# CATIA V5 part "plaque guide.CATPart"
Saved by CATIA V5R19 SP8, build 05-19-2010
Part number: plaque guide
Revision: ANY
Definition: UNKNOWN
Nomenclature: plaque guide
Source: Unknown
Bounding box of the stored display mesh (mm): x 0 to 115.86, y -26.87 to 28, z 0 to 3.4
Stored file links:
  D:\Documents\1_Travail\1 - ac-limoges.fr\ac-limoges.fr\Emmanuel Maynard - STI2D_Turgot\2 -2I2D\2_SEQUENCE_Serrure_Biométrique\5-Spé_ITEC\Serrure_Bio_Eleve\plaque guide.CATPart
  D:\Documents\1_Travail\1 - ac-limoges.fr\ac-limoges.fr\Emmanuel Maynard - STI2D_Turgot\2 -2I2D\2_SEQUENCE_Serrure_Biométrique\5-Spé_ITEC\Serrure_Bio_Eleve\0-serrurebio02_eleve.CATProduct
  D:\Documents\1_Travail\1 - ac-limoges.fr\ac-limoges.fr\Emmanuel Maynard - STI2D_Turgot\2 -2I2D\2_SEQUENCE_Serrure_Biométrique\5-Spé_ITEC\Serrure_Bio_Eleve\axe plaque guide.CATPart
  D:\Documents\1_Travail\1 - ac-limoges.fr\ac-limoges.fr\Emmanuel Maynard - STI2D_Turgot\2 -2I2D\2_SEQUENCE_Serrure_Biométrique\Maquette Numérique SERRURE\SerrureBio02\noix interieure.CATPart
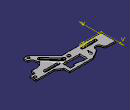
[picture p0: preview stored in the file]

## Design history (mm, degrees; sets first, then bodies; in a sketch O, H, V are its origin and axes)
Set1
  DatumCurve1: linked copy from another document
  DatumCurve2: linked copy from another document
  DatumSurface1: linked copy from another document
Set2
  Sketch1 on face of Solid1, origin (0, 0, 0), H (1, 0, 0), V (0, -1, 0)
    spline S1 through (64.989, -8.5) (67.8652, -8.0494) (69.5066, -6.8457) (86.2254, 11.7224)
    reference projected line E1 (86.2254, 11.7224) -> (69.5066, -6.8457) from edge [face of Solid1 | face of Solid1]
    reference projected line E3 (86.2254, 11.7224) -> (69.5066, -6.8457) from edge [face of Solid1 | face of Solid1]
    reference projected arc E4 centre (65, -6) radius 2.5 from (62.5, -6) to (65, -8.5) ccw from edge [face of Solid1 | face of Solid1]
    reference projected point E5 (86.2254, 11.7224) from edge [face of Solid1 | face of Solid1]
    reference projected point E6 (69.5066, -6.8457) from edge [face of Solid1 | face of Solid1]
    reference projected arc E7 centre (65.7909, -3.5) radius 5 from (65.7909, -8.5) to (69.5066, -6.8457) ccw from edge [face of Solid1 | face of Solid1]
    point P1 (86.2254, 11.7224)
    point P2 (69.5066, -6.8457)
    point P3 (64.989, -8.5)
    point P4 (67.8652, -8.0494)
    coincidence: P1 E1, P2 E3, P3 E4, P1 E5, P2 E6, P4 E7
  Sketch2 on DatumSurface1, origin (0, 0, 3.4), H (1, 0, 0), V (0, 1, 0)
    projected arc E1 centre (36.36, 18.429) radius 3 from (36.36, 15.429) to (36.36, 21.429) ccw from edge of DatumCurve2
Body1 "Congé2" (main body)
  Solid1: solid without history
